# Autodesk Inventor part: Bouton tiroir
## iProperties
Author: Flavien MARTY
Shininess: 20.0
PropertySet Name: _Private Model Information
Created: 2001-10
Part Number: Bouton tiroir
Material: Par défaut
Document SubType Name: Modélisation
Designer: Flavien MARTY
Control State: 0
Master: False
Checked Out: False
PropertySet Name: Design Tracking Control
Density: 0.0
Volumn: 0.0
Area: 0.0
PropertySet Name: Model Information
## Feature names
1. Base1
